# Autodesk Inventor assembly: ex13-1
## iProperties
Author: E. MOSS
Created: 2001-10
Part Number: ex13-1
Document SubType Name: Assembly
Designer: E. MOSS
Control State: 0
Master: False
Checked Out: False
PropertySet Name: Design Tracking Control
Shininess: 64.0
Angle Display Precision: 2
Document Length Units: 11272
Document Angle Units: 11286
Document Time Units: 11279
Document Mass Units: 11290
Document Length Units Precision: 3
Document Angle Units Precision: 2
Compacted: True
PropertySet Name: _Private Model Information
Density: 0.0
Volumn: 0.0
Area: 0.0
PropertySet Name: Model Information
